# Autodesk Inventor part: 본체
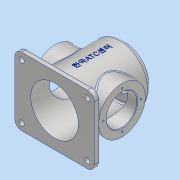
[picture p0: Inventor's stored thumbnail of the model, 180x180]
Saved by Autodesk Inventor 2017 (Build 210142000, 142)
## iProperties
Part Number: 본체
Material: 알루미늄 6061
Document SubType Name: Modeling
Designer: MRC
Density: 2.7 g/cm^3
Appearance: 알루미늄 - 평지
Mass: 1235.53 g
Surface Area: 1067.6 cm^2
Volume: 457.603 cm^3
Author: MRC
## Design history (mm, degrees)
sketch "스케치1"
  geometry: C1 r 50 at (0, 0); 1 further point
  constraints: 1 centre point, 1 coincident
  dimensions: "d0" = 100 diameter of C1
extrude "돌출1" new body sketch "스케치1" stored distance "d1" = 120; taper "d2" = 0 deg
sketch "스케치3"
  geometry: L1 (70, -60)-(-70, -60); L2 (-70, -60)-(-70, 60); L3 (-70, 60)-(70, 60); L4 (70, 60)-(70, -60); L5 (70, -60)-(-70, 60); L6 (-70, -60)-(70, 60); C1 r 50 at (0, 0) reference
  constraints: 12 end point, 2 midpoint, 2 parallel, 1 horizontal, 1 perpendicular
  dimensions: "d3" = 140 distance of L2.end L3.end; "d4" = 120 distance of L1.end L2.end
extrude "돌출2" join sketch "스케치3" distance "d5" = 10; taper "d6" = 0 deg
sketch "스케치4"
  geometry: C1 r 50 at (0, 0) reference; C2 r 41 at (0, 0)
  constraints: 1 centre point, 1 coincident
  dimensions: "d7" = 82 diameter of C2
extrude "돌출3" join sketch "스케치4" distance "d8" = 5; taper "d9" = 0 deg
sketch "스케치5"
  geometry: C1 r 42 at (0, 0); 1 further point
  constraints: 1 centre point, 1 coincident
  dimensions: "d10" = 84 diameter of C1
extrude "돌출4" cut sketch "스케치5" distance "d11" = 112; taper "d12" = 0 deg
sketch "스케치6"
  geometry: C1 r 41 at (0, 0) reference; C2 r 27 at (0, 0)
  constraints: 1 centre point, 1 coincident
  dimensions: "d13" = 54 diameter of C2
extrude "돌출5" cut sketch "스케치6" stored distance "d14" = 112; taper "d15" = 0 deg
node "작업 평면1"
sketch "스케치7"
  geometry: C1 r 41 at (0, 0); 1 further point
  constraints: 1 centre point, 1 coincident
  dimensions: "d17" = 82 diameter of C1
extrude "돌출6" join sketch "스케치7" stored distance "d18" = 112; taper "d19" = 0 deg
sketch "스케치8"
  geometry: C1 r 41 at (0, 0) reference; C2 r 27 at (0, 0)
  constraints: 1 centre point, 1 coincident
  dimensions: "d20" = 54 diameter of C2
extrude "돌출7" cut sketch "스케치8" stored distance "d21" = 112; taper "d22" = 0 deg
sketch "스케치9"
  geometry: C1 r 27 at (0, 0) reference; 1 further point
  constraints: 1 vertical alignment
  dimensions: "d23" = 33 distance of C1.centre point (0, 33)
hole "구멍1" sketch "스케치9" at (0, 33) diameter "d24" = 3.242; stored, may be unused: countersink angle "d28" = 90 deg, drill point angle "d30" = 118 deg; dims "d25" = 8, "d26" = 4, "d27" = 2, "d29" = 10
sketch "스케치10"
  geometry: C1 r 27 at (0, 0) reference; 1 further point
  constraints: 1 vertical alignment
  dimensions: "d34" = 33 distance of C1.centre point (0, 33)
hole "구멍2" sketch "스케치10" at (0, 33) diameter "d35" = 3.242; stored, may be unused: countersink angle "d39" = 90 deg, drill point angle "d41" = 118 deg; dims "d36" = 8, "d37" = 4, "d38" = 2, "d40" = 10
fillet "모깎기1" dims "d45" = 6
fillet "모깎기2" dims "d46" = 12
fillet "모깎기3" dims "d47" = 3
chamfer "모따기1" distance "d48" = 1; stored, may be unused: second distance "d49" = 2, angle "d50" = 45 deg
fillet "모깎기4" dims "d51" = 3
node "작업 평면2"
sketch "스케치11"
  geometry: L1 (-58, -60)-(58, -60) reference; 2 further points
  constraints: 1 vertical alignment, 1 other
  dimensions: "d52" = 66 distance from line of L1 point (0, 6)
feature "엠보싱1" sketch "스케치11" dims "d1" = 120, "d2" = 0, "d53" = 0.5, "d54" = 0
sketch "스케치12"
  geometry: C1 r 4.5 at (-58, 48); C2 r 4.5 at (58, 48); C3 r 4.5 at (58, -48); C4 r 4.5 at (-58, -48); A1 r 9 centre (58, -48) between (58, -57) and (67, -48) reference; A2 r 9 centre (58, 48) between (67, 48) and (58, 57) reference; A3 r 9 centre (-58, 48) between (-58, 57) and (-67, 48) reference; A4 r 9 centre (-58, -48) between (-67, -48) and (-58, -57) reference
  constraints: 4 centre point, 4 coincident
  dimensions: "d55" = 9 diameter of C1; "d56" = 9 diameter of C2; "d57" = 9 diameter of C3; "d58" = 9 diameter of C4
extrude "돌출8" cut sketch "스케치12" stored distance "d59" = 112; taper "d60" = 0 deg
node "솔리드1"
pattern_circular "원형 패턴1" dims angle "d32" = 360 deg
mirror "미러1"
pattern_circular "원형 패턴2" dims angle "d43" = 360 deg
other parameters: "d16" = 59
